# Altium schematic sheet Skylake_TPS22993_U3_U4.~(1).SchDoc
size 431 x 279 mm; Date: Not shown in title block; ApprovedBy: Not shown in title block; CheckedBy: Not shown in title block; Author: Not shown in title block; CompanyName: Not shown in title block; Engineer: Not shown in title block; Organization: Not shown in title block; Address1: Not shown in title block; Address2: Not shown in title block; Address3: Not shown in title block; Address4: Not shown in title block; DocumentNumber: 1; Revision: Use project parameter SCH_Rev; SheetNumber: 2; SheetTotal: 9; PageSetup: Record=PageOptions|CenterHorizontal=True|CenterVertical=True|PrintScale=1.00|XCorrection=1.00|YCorrection=1.00|PrintKind=0|BorderSize=5000000|LeftOffset=0|BottomOffset=0|Orientation=2|PaperLength=1000|PaperWidth=1000|Scale=100|PaperSource=15|PrintQuality=600|MediaType=1|DitherType=10|PaperKind=Letter|PrintScaleMode=1
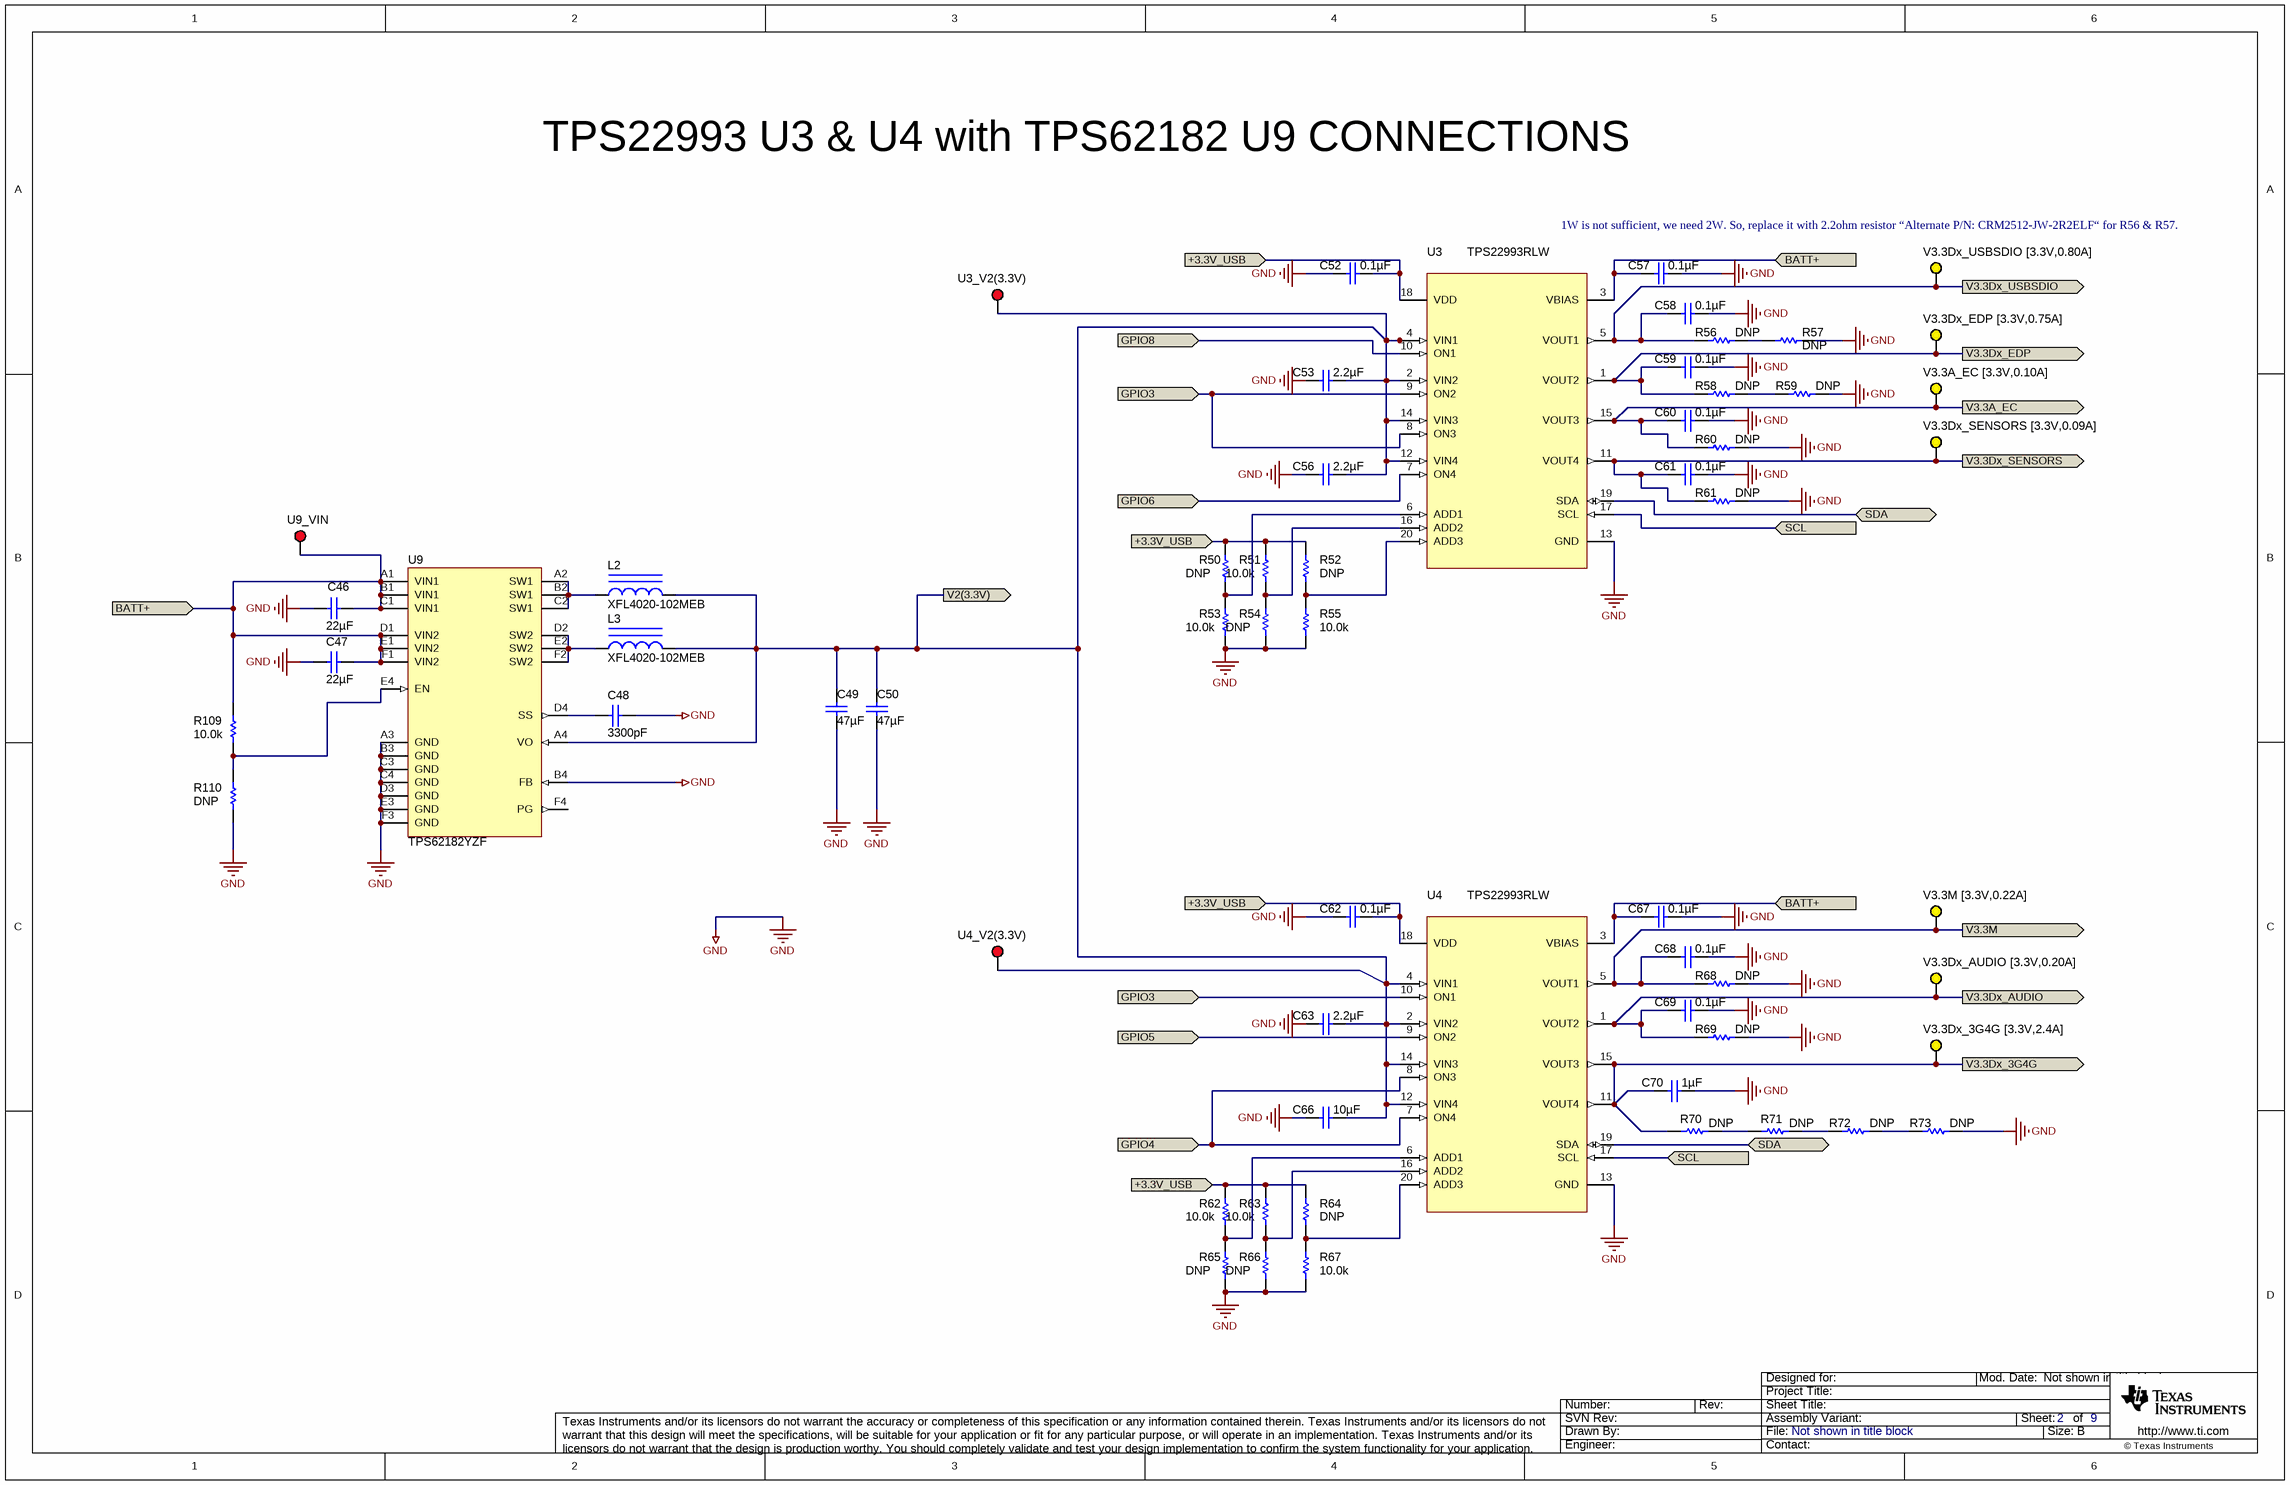
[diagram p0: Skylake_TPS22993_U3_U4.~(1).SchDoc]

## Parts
C46  ValueDisplayed: 22µF  [0805_HV]  (hidden comment: C2012JB1V226M125AC)
C47  ValueDisplayed: 22µF  [0805_HV]  (hidden comment: C2012JB1V226M125AC)
C48  ValueDisplayed: 3300pF  [0603]  (hidden comment: C0603C332J3RACTU)
C49  ValueDisplayed: 47µF  [0805_HV]  (hidden comment: C2012X5R1A476M125AC)
C50  ValueDisplayed: 47µF  [0805_HV]  (hidden comment: C2012X5R1A476M125AC)
C52  ValueDisplayed: 0.1µF  [0603]  (hidden comment: C0603C104K8RACTU)
C53  ValueDisplayed: 2.2µF  [0603]  (hidden comment: GRM188C81A225KE34D)
C56  ValueDisplayed: 2.2µF  [0603]  (hidden comment: GRM188C81A225KE34D)
C57  ValueDisplayed: 0.1µF  [0805_HV]  (hidden comment: GMK212BJ104KGHT)
C58  ValueDisplayed: 0.1µF  [0603]  (hidden comment: C0603C104K8RACTU)
C59  ValueDisplayed: 0.1µF  [0603]  (hidden comment: C0603C104K8RACTU)
C60  ValueDisplayed: 0.1µF  [0603]  (hidden comment: C0603C104K8RACTU)
C61  ValueDisplayed: 0.1µF  [0603]  (hidden comment: C0603C104K8RACTU)
C62  ValueDisplayed: 0.1µF  [0603]  (hidden comment: C0603C104K8RACTU)
C63  ValueDisplayed: 2.2µF  [0603]  (hidden comment: GRM188C81A225KE34D)
C66  ValueDisplayed: 10µF  [0805_HV]  (hidden comment: C2012JB1V106K085AC)
C67  ValueDisplayed: 0.1µF  [0805_HV]  (hidden comment: GMK212BJ104KGHT)
C68  ValueDisplayed: 0.1µF  [0603]  (hidden comment: C0603C104K8RACTU)
C69  ValueDisplayed: 0.1µF  [0603]  (hidden comment: C0603C104K8RACTU)
C70  ValueDisplayed: 1µF  [0603]  (hidden comment: C0603C105K8PACTU)
L2  XFL4020-102MEB  [XFL4020]
L3  XFL4020-102MEB  [XFL4020]
R50  value DNP  [0402]  (hidden comment: CRCW040210K0FKED)
R51  value 10.0k  [0402]  (hidden comment: CRCW040210K0FKED)
R52  value DNP  [0402]  (hidden comment: CRCW040210K0FKED)
R53  value 10.0k  [0402]  (hidden comment: CRCW040210K0FKED)
R54  value DNP  [0402]  (hidden comment: CRCW040210K0FKED)
R55  value 10.0k  [0402]  (hidden comment: CRCW040210K0FKED)
R56  value DNP  [2512M]  (hidden comment: CRM2512-JW-2R2ELF)
R57  value DNP  [2512M]  (hidden comment: CRM2512-JW-2R2ELF)
R58  value DNP  [2512M]  (hidden comment: CRM2512-JW-2R2ELF)
R59  value DNP  [2512M]  (hidden comment: CRM2512-JW-2R2ELF)
R60  value DNP  [2512M]  (hidden comment: RMCF2512JT33R0)
R61  value DNP  [2512M]  (hidden comment: CRCW251236R5FKEG)
R62  value 10.0k  [0402]  (hidden comment: CRCW040210K0FKED)
R63  value 10.0k  [0402]  (hidden comment: CRCW040210K0FKED)
R64  value DNP  [0402]  (hidden comment: CRCW040210K0FKED)
R65  value DNP  [0402]  (hidden comment: CRCW040210K0FKED)
R66  value DNP  [0402]  (hidden comment: CRCW040210K0FKED)
R67  value 10.0k  [0402]  (hidden comment: CRCW040210K0FKED)
R68  value DNP  [2512M]  (hidden comment: CRCW251215R0FKEG)
R69  value DNP  [2512M]  (hidden comment: RMCF2512FT16R5)
R70  value DNP  [PWR5322]  (hidden comment: PWR5322WR500JE)
R71  value DNP  [PWR5322]  (hidden comment: PWR5322WR500JE)
R72  value DNP  [2512M]  (hidden comment: RLP73K3AR22JTE)
R73  value DNP  [2512M]  (hidden comment: RLP73K3AR22JTE)
R109  value 10.0k  [0402]  (hidden comment: CRCW040210K0FKED)
R110  value DNP  [0402]  (hidden comment: CRCW040210K0FKED)
U3  TPS22993RLW  [RLW0020A]
U3_V2(3.3V)  5005  [Keystone5005]  (value not drawn)
U4  TPS22993RLW  [RLW0020A]
U4_V2(3.3V)  5005  [Keystone5005]  (value not drawn)
U9  TPS62182YZF  [YZF0024AMAM]
U9_VIN  5005  [Keystone5005]  (value not drawn)
V3.3A_EC_[3.3V,0.10A]  5009  [Keystone5009]  (value not drawn)
V3.3Dx_3G4G_[3.3V,2.4A]  5009  [Keystone5009]  (value not drawn)
V3.3Dx_AUDIO_[3.3V,0.20A]  5009  [Keystone5009]  (value not drawn)
V3.3Dx_EDP_[3.3V,0.75A]  5009  [Keystone5009]  (value not drawn)
V3.3Dx_SENSORS_[3.3V,0.09A]  5009  [Keystone5009]  (value not drawn)
V3.3Dx_USBSDIO_[3.3V,0.80A]  5009  [Keystone5009]  (value not drawn)
V3.3M_[3.3V,0.22A]  5009  [Keystone5009]  (value not drawn)

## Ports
+3.3V_USB (in), BATT+ (in), GPIO3 (in), GPIO4 (in), GPIO5 (in), GPIO6 (in), GPIO8 (in), SCL (in), SDA (bidir), V2(3.3V) (out), V3.3A_EC (out), V3.3Dx_3G4G (out), V3.3Dx_AUDIO (out), V3.3Dx_EDP (out), V3.3Dx_SENSORS (out), V3.3Dx_USBSDIO (out), V3.3M (out)

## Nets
GND: C46.2 C47.2 C48.1 C49.2 C50.2 C52.2 C53.2 C56.2 C57.1 C58.1 C59.1 C60.1 C61.1 C62.2 C63.2 C66.2 C67.1 C68.1 C69.1 C70.1 R53.1 R54.1 R55.1 R57.2 R59.2 R60.2 R61.2 R65.1 R66.1 R67.1 R68.2 R69.2 R73.2 R110.1 U3.13(GND) U4.13(GND) U9.A3(GND) U9.B3(GND) U9.B4(FB) U9.C3(GND) U9.C4(GND) U9.D3(GND) U9.E3(GND) U9.F3(GND)
+3.3V_USB: C52.1 C62.1 R50.2 R51.2 R52.2 R62.2 R63.2 R64.2 U3.18(VDD) U4.18(VDD) ; port +3.3V_USB
BATT+: C46.1 C47.1 C57.2 C67.2 R109.2 U3.3(VBIAS) U4.3(VBIAS) U9.A1(VIN1) U9.B1(VIN1) U9.C1(VIN1) U9.D1(VIN2) U9.E1(VIN2) U9.F1(VIN2) U9_VIN.1 ; port BATT+
GPIO3: U3.8(ON3) U3.9(ON2) U4.10(ON1) ; port GPIO3
GPIO4: U4.7(ON4) U4.8(ON3) ; port GPIO4
GPIO5: U4.9(ON2) ; port GPIO5
GPIO6: U3.7(ON4) ; port GPIO6
GPIO8: U3.10(ON1) ; port GPIO8
SCL: U3.17(SCL) U4.17(SCL) ; port SCL
SDA: U3.19(SDA) U4.19(SDA) ; port SDA
V2(3.3V): C49.1 C50.1 C53.1 C56.1 C63.1 C66.1 L2.2 L3.2 U3.2(VIN2) U3.4(VIN1) U3.12(VIN4) U3.14(VIN3) U3_V2(3.3V).1 U4.2(VIN2) U4.4(VIN1) U4.12(VIN4) U4.14(VIN3) U4_V2(3.3V).1 U9.A4(VO) ; port V2(3.3V)
V3.3A_EC: C60.2 R60.1 U3.15(VOUT3) V3.3A_EC_[3.3V,0.10A].1 ; port V3.3A_EC
V3.3Dx_3G4G: C70.2 R70.1 U4.11(VOUT4) U4.15(VOUT3) V3.3Dx_3G4G_[3.3V,2.4A].1 ; port V3.3Dx_3G4G
V3.3Dx_AUDIO: C69.2 R69.1 U4.1(VOUT2) V3.3Dx_AUDIO_[3.3V,0.20A].1 ; port V3.3Dx_AUDIO
V3.3Dx_EDP: C59.2 R58.1 U3.1(VOUT2) V3.3Dx_EDP_[3.3V,0.75A].1 ; port V3.3Dx_EDP
V3.3Dx_SENSORS: C61.2 R61.1 U3.11(VOUT4) V3.3Dx_SENSORS_[3.3V,0.09A].1 ; port V3.3Dx_SENSORS
V3.3Dx_USBSDIO: C58.2 R56.1 U3.5(VOUT1) V3.3Dx_USBSDIO_[3.3V,0.80A].1 ; port V3.3Dx_USBSDIO
V3.3M: C68.2 R68.1 U4.5(VOUT1) V3.3M_[3.3V,0.22A].1 ; port V3.3M
NetC48_2: C48.2 U9.D4(SS)
NetL2_1: L2.1 U9.A2(SW1) U9.B2(SW1) U9.C2(SW1)
NetL3_1: L3.1 U9.D2(SW2) U9.E2(SW2) U9.F2(SW2)
NetR50_1: R50.1 R53.2 U3.6(ADD1)
NetR51_1: R51.1 R54.2 U3.16(ADD2)
NetR52_1: R52.1 R55.2 U3.20(ADD3)
NetR56_2: R56.2 R57.1
NetR58_2: R58.2 R59.1
NetR62_1: R62.1 R65.2 U4.6(ADD1)
NetR63_1: R63.1 R66.2 U4.16(ADD2)
NetR64_1: R64.1 R67.2 U4.20(ADD3)
NetR70_2: R70.2 R71.1
NetR71_2: R71.2 R72.1
NetR72_2: R72.2 R73.1
NetR109_1: R109.1 R110.2 U9.E4(EN)

Not connected (* = marked no-connect by the designer): U9 F4(PG)

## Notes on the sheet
- TPS22993 U3 & U4 with TPS62182 U9 CONNECTIONS
- 1W is not sufficient, we need 2W. So, replace it with 2.2ohm resistor “Alternate P/N: CRM2512-JW-2R2ELF“ for R56 & R57.

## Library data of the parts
C46 C47 = GRM21BR61E226ME44: CAP, CERM, 22uF, 35V, +/-20%, X5R, 0805; Manufacturer: TDK Corporation; Polarized: N; CompType: Capacitor; U/M: EA; Cap_F: 0.000022; Tolerance_%: 20; Value1: Unknown; VDC_V: 35; TaMin_C: -55; TaMax_C: 85; Cap_Case: 0805
C48 = C0603C332K5RACTU: CAP, CERM, 3300pF, 25V, +/-5%, X7R, 0603; Manufacturer: Kemet; Polarized: N; CompType: Capacitor; U/M: EA; Cap_F: 0.0000000033; Tolerance_%: 5; Value1: Unknown; VDC_V: 25; TaMin_C: -55; TaMax_C: 125
C49 C50 = GRM21BR61E226ME44: CAP, CERM, 47uF, 10V, +/-20%, X5R, 0805; Manufacturer: TDK Corporation; Polarized: N; CompType: Capacitor; U/M: EA; Cap_F: 0.000022; Tolerance_%: 20; Value1: Unknown; VDC_V: 10; TaMin_C: -55; TaMax_C: 85; Cap_Case: 0805
C52 C58-C62 C68 C69 = GRM188R71C104KA01D: CAP, CERM, 0.1uF, 10V, +/-10%, X7R, 0603; Manufacturer: Kemet; Polarized: N; CompType: Capacitor; U/M: EA; Cap_F: 0.0000001; Tolerance_%: 10; Value1: Unknown; TaMin_C: -55; TaMax_C: 125
C53 C56 C63 = GRM188C81A225KE34D: CAP, CERM, 2.2uF, 10V, +/-10%, X6S, 0603; Manufacturer: MuRata; Polarized: N; CompType: Capacitor; U/M: EA; Cap_F: 0.0000022; Tolerance_%: 10; Value1: Unknown; TaMin_C: -55; TaMax_C: 105
C57 C67 = GRM21BR61E226ME44: CAP, CERM, 0.1uF, 35V, +/-20%, X5R, 0805; Manufacturer: Taiyo Yuden; Polarized: N; CompType: Capacitor; U/M: EA; Cap_F: 0.000022; Tolerance_%: 20; Value1: Unknown; VDC_V: 35; TaMin_C: -55; TaMax_C: 85; Cap_Case: 0805
C66 = GRM21BR61E226ME44: CAP, CERM, 10uF, 35V, +/-10%, X5R, 0805; Manufacturer: TDK Corporation; Polarized: N; CompType: Capacitor; U/M: EA; Cap_F: 0.000022; Tolerance_%: 20; Value1: Unknown; VDC_V: 35; TaMin_C: -55; TaMax_C: 85; Cap_Case: 0805
C70 = C0603C105K8PACTU: CAP, CERM, 1uF, 10V, +/-10%, X5R, 0603; Manufacturer: Kemet; Polarized: N; CompType: Capacitor; U/M: EA; Cap_F: 0.000001; Tolerance_%: 10; Value1: Unknown; TaMin_C: -55; TaMax_C: 85
L2 L3 = XFL4020-102MEB: Inductor, Shielded, Composite, 1uH, 5.4A, 0.01 ohm, SMD; Manufacturer: Coilcraft; Ind_H: 1.0E-6; ValueDisplayed: 1µH; Imax_A: 5.4; Irms: 11A @ 40C rise; Isat: 5.4A @ 30% inductance drop; DCR_ohm: 0.01; U/M: EA
R50 R52 R54 R64-R66 R110 = CRCW040210K0FKED: RES, DNP, 1%, 0.063W, 0402; Manufacturer: Vishay-Dale; CompType: Resistor; Res_ohm: 10000; Value_Code: 10k0; Tolerance_%: 1; Power_W: 0.063; VDC_V: 50; TempCo: 100 ppm/C; EIA_Code: E96; U/M: EA
R51 R53 R55 R62 R63 R67 R109 = CRCW040210K0FKED: RES, 10.0k ohm, 1%, 0.063W, 0402; Manufacturer: Vishay-Dale; CompType: Resistor; Res_ohm: 10000; Value_Code: 10k0; Tolerance_%: 1; Power_W: 0.063; VDC_V: 50; TempCo: 100 ppm/C; EIA_Code: E96; U/M: EA
R56 = CSNL2512FT2L00: RES, DNP, 5%, 2W, 2512; Manufacturer: Bourns Inc; CompType: Resistor; Res_ohm: 2.2; Tolerance_%: 5; Power_W: 2; VDC_V: 200; TempCo: 50 ppm/C; U/M: EA
R57 = CSNL2512FT2L00: RES, DNP, 1%, 2W, 2512; Manufacturer: Bourns Inc.; CompType: Resistor; Res_ohm: 2.2; Tolerance_%: 5; Power_W: 2; VDC_V: 200; TempCo: 50 ppm/C; U/M: EA
R58 R59 = CSNL2512FT2L00: RES, DNP, 5%, 2W, 2512; Manufacturer: Bourns Inc.; CompType: Resistor; Res_ohm: 2.2; Tolerance_%: 5; Power_W: 2; VDC_V: 200; TempCo: 50 ppm/C; U/M: EA
R60 = CSNL2512FT2L00: RES, DNP, 5%, 1W, 2512; Manufacturer: Stackpole Electronics Inc; CompType: Resistor; Res_ohm: 33; Tolerance_%: 1; VDC_V: 200; TempCo: 50 ppm/C; U/M: EA
R61 = CSNL2512FT2L00: RES, DNP, 1%, 1W, 2512; Manufacturer: Vishay Dale; CompType: Resistor; Res_ohm: 36.5; Tolerance_%: 1; VDC_V: 200; TempCo: 50 ppm/C; U/M: EA
R68 = CSNL2512FT2L00: RES, DNP, 1%, 1W, 2512; Manufacturer: Vishay Dale; CompType: Resistor; Res_ohm: 15; Tolerance_%: 1; VDC_V: 200; TempCo: 50 ppm/C; U/M: EA
R69 = CSNL2512FT2L00: RES, DNP, 1%, 1W, 2512; Manufacturer: Stackpole Electronics Inc; CompType: Resistor; Res_ohm: 16.5; Tolerance_%: 1; VDC_V: 200; TempCo: 50 ppm/C; U/M: EA
R70 R71 = PWR5322WR500JE: RES, DNP, 5%, 3W, 13.5x5.65x5.5mm; Manufacturer: Bourns; CompType: Resistor; Res_ohm: 0.5; Value_Code: R500; Tolerance_%: 5; Power_W: 3; TempCo: 90 ppm/C; U/M: EA
R72 R73 = CRCW25121K10JNEG: RES, DNP, 5%, 2W, 2512; Manufacturer: TE Connectivity; CompType: Resistor; Tolerance_%: 5; Power_W: 2; VDC_V: 500; TempCo: 200 ppm/C; EIA_Code: E24; U/M: EA
U3 U4 = TPS22993RLW: Quad Channel Load Switch with GPIO and I2C Control, RLW0020A; Alternate Manufacturer: None; Manufacturer: Texas Instruments; SymbolCreator: a0411947; CompType: IC; U/M: EA
U3_V2(3.3V) U4_V2(3.3V) U9_VIN = 5005: Test Point, Compact, Red, TH; Manufacturer: Keystone; CompType: Test Point Loop; U/M: EA
U9 = TPS62180YZF: 4 - 17V, 6A, 2-Phase Step-Down Converter, YZF0024AMAM; Alternate Manufacturer: None; Manufacturer: Texas Instruments; SymbolCreator: a0799628; CompType: IC; U/M: EA
V3.3A_EC_[3.3V,0.10A] V3.3Dx_3G4G_[3.3V,2.4A] V3.3Dx_AUDIO_[3.3V,0.20A] V3.3Dx_EDP_[3.3V,0.75A] V3.3Dx_SENSORS_[3.3V,0.09A] V3.3Dx_USBSDIO_[3.3V,0.80A] V3.3M_[3.3V,0.22A] = 5009: Test Point, Compact, Yellow, TH; Manufacturer: Keystone; CompType: Test Point Loop; U/M: EA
